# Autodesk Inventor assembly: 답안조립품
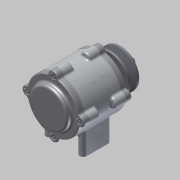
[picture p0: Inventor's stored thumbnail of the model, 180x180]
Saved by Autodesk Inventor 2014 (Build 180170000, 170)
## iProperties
Created: 2015-03
Part Number: 답안조립품
Document SubType Name: Assembly
Designer: MYHOME
Author: MYHOME
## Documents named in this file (11)
- C:\Documents and Settings\MYHOME\바탕 화면\450306V1018\답안조립품.iam
- C:\Documents and Settings\MYHOME\바탕 화면\450306V1018\본체.ipt
- C:\Documents and Settings\MYHOME\바탕 화면\450306V1018\커버2.ipt
- C:\Documents and Settings\MYHOME\바탕 화면\450306V1018\커버.ipt
- C:\Documents and Settings\MYHOME\바탕 화면\450306V1018\M 4 x 12.ipt
- C:\Documents and Settings\MYHOME\바탕 화면\450306V1018\축.ipt
- C:\Documents and Settings\MYHOME\바탕 화면\450306V1018\베어링 6204.ipt
- C:\Documents and Settings\MYHOME\바탕 화면\450306V1018\오일실.ipt
- C:\Documents and Settings\MYHOME\바탕 화면\450306V1018\키(4 x 4 x 12).ipt
- C:\Documents and Settings\MYHOME\바탕 화면\450306V1018\V벨트풀리.ipt
- C:\Documents and Settings\MYHOME\바탕 화면\450306V1018\너트 M12x1.25.ipt
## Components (14 placed, 6 different names)
1. KS B 2023 6204 - 20 x 47 x 14:1 — 각도:1
2. KS B 2023 6204 - 20 x 47 x 14:2 — 각도:2
3. KS B 2804 D D - 20 32 8:1
4. KS B 1311 (I) 4 x 4 x 12:1
5. 그루브 풀리1:1
6. KS B 1012 클래스 1 일반 - 미터 M12x1.25:1 — 각도:3
7. KS B 1003 - 미터 M 4 x 12:2
8. KS B 1003 - 미터 M 4 x 12:3
9. KS B 1003 - 미터 M 4 x 12:4
10. KS B 1003 - 미터 M 4 x 12:5
11. KS B 1003 - 미터 M 4 x 12:1
12. KS B 1003 - 미터 M 4 x 12:6
13. KS B 1003 - 미터 M 4 x 12:7
14. KS B 1003 - 미터 M 4 x 12:8
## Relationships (3: Angle 3)
- 각도:1 [Angle]: KS B 2023 6204 - 20 x 47 x 14:1
- 각도:2 [Angle]: KS B 2023 6204 - 20 x 47 x 14:2
- 각도:3 [Angle]: KS B 1012 클래스 1 일반 - 미터 M12x1.25:1
